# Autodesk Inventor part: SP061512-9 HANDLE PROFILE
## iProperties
Created: 2012-06
Part Number: SP061512-9 HANDLE PROFILE
Material: Aluminum-6061
Description: HANDLE PROFILE 32
Document SubType Name: Modeling
Designer: Administrator
Stock Number: 20.1088 HANDLE PROFILE 32
Density: 2.71 g/cm^3
Mass: 557.464 g
Surface Area: 1676.36 cm^2
Volume: 205.706 cm^3
FINISH: CLEAR ANODIZED
Author: Administrator
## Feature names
1. Extrusion1
